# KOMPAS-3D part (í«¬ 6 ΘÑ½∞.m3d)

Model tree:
1. Эскиз:1
2. Операция выдавливания:1
     Расстояние 1 = 2
3. Эскиз:2
4. Операция выдавливания:2
     Расстояние 1 = 5
5. Эскиз:3
6. Операция выдавливания:3
     Расстояние 1 = 2
7. Эскиз:4
8. Операция выдавливания:4
     Расстояние 1 = 60
9. Эскиз:5
10. Операция выдавливания:5
     Расстояние 1 = 2
11. Эскиз:6
12. Операция выдавливания:6
     Расстояние 1 = 4.5
13. Эскиз:7
14. Операция выдавливания:7
     Расстояние 1 = 2
15. Скругление:1
     Радиус = 1
16. Скругление:2
     Радиус = 1
17. Эскиз:8
18. Вырезать элемент выдавливания:1
     Расстояние 1 = 10; Угол 1 = 35
19. Эскиз:9
20. Вырезать элемент выдавливания:2
     Расстояние 1 = 10; Угол 1 = 35
21. Эскиз:10
22. Вырезать элемент выдавливания:3
     Расстояние 2 = 22; Расстояние 1 = 22; Угол 1 = 35
23. Эскиз:11
24. Вырезать элемент выдавливания:4
     Расстояние 2 = 2; Расстояние 1 = 2
25. Эскиз:12
26. Вырезать элемент выдавливания:5
     Расстояние 2 = 2; Расстояние 1 = 2; Угол 1 = 35
27. Эскиз:13
28. Вырезать элемент выдавливания:6
     Расстояние 2 = 2; Расстояние 1 = 122
29. Эскиз:16
30. Операция выдавливания:10
     Расстояние 1 = 4
31. Вырезать элемент выдавливания:7
     Расстояние 1 = 90
32. Эскиз:17
33. Вырезать элемент выдавливания:8
     Расстояние 1 = 90
